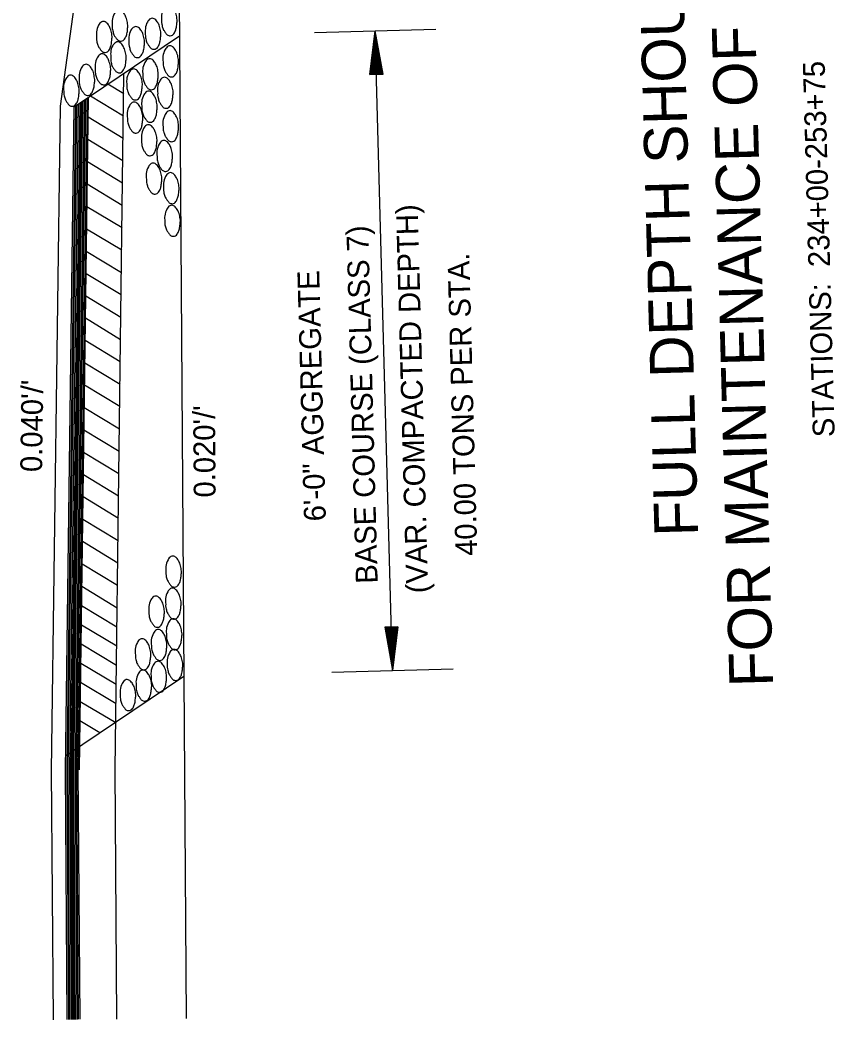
# Model space of a CAD drawing. Extents: x 1926836 to 1933254, y 596317 to 604524.
# Drawn here: x 1932668 to 1932892, y 597228.4 to 597503.4 of the extents above; entities that cross this region are included whole.
import ezdxf

# ---------------------------------------------------------------- set-up
doc = ezdxf.new("R2010")
doc.units = 0
doc.layers.add('Default', color=7, linetype='Continuous')

msp = doc.modelspace()

# ---------------------------------------------------------------- linework, layer by layer
at = {"layer": 'Default'}
for p, q in [((1932679.06, 597479.65), (1932733.75, 597872.49)), ((1932713.69, 597228.79), (1932710.43, 597704.89)), ((1932682.89, 597479.47), (1932711.83, 597498.96)), ((1932748.97, 597499.95), (1932782.32, 597500.85)), ((1932764.17, 597488.36), (1932765.65, 597500.4)), ((1932764.47, 597488.36), (1932765.7, 597498.4)), ((1932770.37, 597324.49), (1932765.65, 597500.4)), ((1932767.77, 597488.45), (1932765.65, 597500.4)), ((1932767.47, 597488.44), (1932765.7, 597498.4)), ((1932764.78, 597488.37), (1932765.75, 597496.33)), ((1932767.16, 597488.44), (1932765.75, 597496.33)), ((1932765.08, 597488.38), (1932765.81, 597494.33)), ((1932766.86, 597488.43), (1932765.81, 597494.33)), ((1932765.39, 597488.39), (1932765.86, 597492.3)), ((1932765.69, 597488.4), (1932765.92, 597490.3)), ((1932766.56, 597488.42), (1932765.86, 597492.3)), ((1932766.25, 597488.41), (1932765.92, 597490.3)), ((1932694.13, 597297.28), (1932696.55, 597488.66)), ((1932764.17, 597488.36), (1932767.77, 597488.45)), ((1932696.48, 597483.08), (1932692.13, 597485.72)), ((1932684.3, 597297.21), (1932686.76, 597482.07)), ((1932696.4, 597476.95), (1932687.31, 597482.44)), ((1932676.65, 597297.01), (1932679.06, 597479.53)), ((1932680.45, 597297.11), (1932682.89, 597479.47)), ((1932680.89, 597297.12), (1932683.33, 597479.76)), ((1932681.22, 597297.13), (1932683.61, 597479.96)), ((1932681.64, 597297.14), (1932684.07, 597480.28)), ((1932682.06, 597297.15), (1932684.46, 597480.51)), ((1932682.42, 597297.16), (1932684.89, 597480.81)), ((1932682.8, 597297.17), (1932685.23, 597481.03)), ((1932683.18, 597297.18), (1932685.66, 597481.37)), ((1932683.6, 597297.19), (1932686.05, 597481.62)), ((1932683.97, 597297.2), (1932686.48, 597481.89)), ((1932696.32, 597470.77), (1932686.66, 597476.64)), ((1932696.24, 597464.61), (1932686.59, 597470.49)), ((1932696.16, 597458.48), (1932686.51, 597464.34)), ((1932696.08, 597452.36), (1932686.43, 597458.21)), ((1932696.01, 597446.18), (1932686.36, 597452.02)), ((1932695.93, 597440.06), (1932686.26, 597445.88)), ((1932695.85, 597433.86), (1932686.17, 597439.74)), ((1932695.78, 597427.77), (1932686.13, 597433.6)), ((1932695.7, 597421.58), (1932686.02, 597427.46)), ((1932695.62, 597415.42), (1932685.96, 597421.34)), ((1932695.54, 597409.33), (1932685.87, 597415.2)), ((1932695.47, 597403.16), (1932685.76, 597409.02)), ((1932695.39, 597397.04), (1932685.67, 597402.93)), ((1932695.32, 597390.82), (1932685.62, 597396.75)), ((1932695.23, 597384.74), (1932685.55, 597390.61)), ((1932695.16, 597378.58), (1932685.45, 597384.47)), ((1932695.08, 597372.42), (1932685.38, 597378.3)), ((1932695.01, 597366.32), (1932685.28, 597372.21)), ((1932694.92, 597360.12), (1932685.19, 597366.03)), ((1932694.84, 597353.98), (1932685.13, 597359.92)), ((1932694.77, 597347.82), (1932685.06, 597353.73)), ((1932694.69, 597341.66), (1932684.98, 597347.59)), ((1932694.62, 597336.44), (1932684.87, 597342.24)), ((1932694.56, 597331.19), (1932684.82, 597336.96)), ((1932771.84, 597336.54), (1932768.25, 597336.44)), ((1932768.25, 597336.44), (1932770.37, 597324.49)), ((1932768.55, 597336.45), (1932770.31, 597326.49)), ((1932768.86, 597336.46), (1932770.26, 597328.56)), ((1932769.16, 597336.46), (1932770.2, 597330.56)), ((1932769.46, 597336.47), (1932770.15, 597332.59)), ((1932769.77, 597336.48), (1932770.1, 597334.59)), ((1932770.33, 597336.5), (1932770.1, 597334.59)), ((1932770.63, 597336.5), (1932770.15, 597332.59)), ((1932770.94, 597336.51), (1932770.2, 597330.56)), ((1932771.23, 597336.52), (1932770.26, 597328.56)), ((1932771.54, 597336.53), (1932770.31, 597326.49)), ((1932771.84, 597336.54), (1932770.37, 597324.49)), ((1932694.49, 597325.89), (1932684.73, 597331.7)), ((1932694.42, 597320.6), (1932684.7, 597326.45)), ((1932680.49, 597301.03), (1932713.03, 597322.95)), ((1932753.69, 597324.05), (1932787.04, 597324.94)), ((1932694.36, 597315.33), (1932684.59, 597321.16)), ((1932694.29, 597310.08), (1932684.53, 597315.9)), ((1932689.94, 597307.39), (1932684.45, 597310.65)), ((1932677.12, 597228.39), (1932676.65, 597297.01)), ((1932680.94, 597228.49), (1932680.45, 597297.11)), ((1932681.36, 597228.5), (1932680.89, 597297.12)), ((1932681.68, 597228.51), (1932681.22, 597297.13)), ((1932682.09, 597228.52), (1932681.64, 597297.14)), ((1932682.49, 597228.53), (1932682.06, 597297.15)), ((1932682.87, 597228.54), (1932682.42, 597297.16)), ((1932683.26, 597228.55), (1932682.8, 597297.17)), ((1932683.65, 597228.56), (1932683.18, 597297.18)), ((1932684.08, 597228.57), (1932683.6, 597297.19)), ((1932684.46, 597228.58), (1932683.97, 597297.2)), ((1932694.62, 597228.66), (1932694.13, 597297.28))]:
    msp.add_line(p, q, dxfattribs=at)
for points in [[(1932706.88, 597503.14), (1932706.88, 597504.68), (1932707.44, 597506.52), (1932708.29, 597507.43), (1932708.78, 597507.56), (1932709.75, 597507.11), (1932710.17, 597506.61), (1932710.67, 597505.65), (1932711.07, 597504.18), (1932711.15, 597503.41), (1932711.09, 597502.31), (1932710.91, 597501.08), (1932710.56, 597500.1), (1932709.89, 597499.2), (1932709.28, 597499.03), (1932708.44, 597499.27), (1932707.9, 597499.94), (1932707.45, 597500.59), (1932707.09, 597501.57), (1932706.95, 597502.21), (1932706.88, 597503.14)], [(1932693.32, 597501.7), (1932693.29, 597503.18), (1932693.88, 597505.04), (1932694.72, 597505.93), (1932695.22, 597506.1), (1932696.16, 597505.66), (1932696.58, 597505.13), (1932697.09, 597504.15), (1932697.51, 597502.7), (1932697.57, 597501.92), (1932697.54, 597500.83), (1932697.37, 597499.58), (1932696.99, 597498.62), (1932696.31, 597497.71), (1932695.73, 597497.55), (1932694.89, 597497.81), (1932694.31, 597498.48), (1932693.86, 597499.08), (1932693.54, 597500.1), (1932693.36, 597500.74), (1932693.32, 597501.7)], [(1932689.01, 597498.56), (1932688.99, 597500.07), (1932689.56, 597501.9), (1932690.41, 597502.84), (1932690.89, 597502.96), (1932691.85, 597502.53), (1932692.27, 597502.01), (1932692.78, 597501.04), (1932693.19, 597499.57), (1932693.27, 597498.82), (1932693.19, 597497.69), (1932693.02, 597496.46), (1932692.68, 597495.48), (1932691.97, 597494.59), (1932691.4, 597494.42), (1932690.58, 597494.66), (1932690, 597495.35), (1932689.57, 597495.98), (1932689.21, 597496.99), (1932689.05, 597497.59), (1932689.01, 597498.56)], [(1932697.91, 597497.13), (1932697.91, 597498.67), (1932698.47, 597500.52), (1932699.31, 597501.43), (1932699.81, 597501.54), (1932700.77, 597501.11), (1932701.2, 597500.6), (1932701.7, 597499.63), (1932702.1, 597498.16), (1932702.18, 597497.41), (1932702.12, 597496.29), (1932701.94, 597495.07), (1932701.59, 597494.1), (1932700.91, 597493.19), (1932700.31, 597493.01), (1932699.47, 597493.26), (1932698.92, 597493.94), (1932698.47, 597494.57), (1932698.12, 597495.57), (1932697.97, 597496.2), (1932697.91, 597497.13)], [(1932702.41, 597499.42), (1932702.42, 597500.96), (1932702.98, 597502.8), (1932703.82, 597503.71), (1932704.32, 597503.84), (1932705.28, 597503.39), (1932705.7, 597502.89), (1932706.21, 597501.93), (1932706.6, 597500.46), (1932706.69, 597499.69), (1932706.62, 597498.59), (1932706.44, 597497.36), (1932706.09, 597496.38), (1932705.42, 597495.48), (1932704.81, 597495.31), (1932703.98, 597495.55), (1932703.44, 597496.22), (1932702.98, 597496.87), (1932702.62, 597497.85), (1932702.48, 597498.48), (1932702.41, 597499.42)], [(1932692.92, 597492.98), (1932692.9, 597494.46), (1932693.44, 597496.31), (1932694.29, 597497.2), (1932694.78, 597497.38), (1932695.74, 597496.93), (1932696.16, 597496.4), (1932696.65, 597495.43), (1932697.07, 597493.98), (1932697.15, 597493.2), (1932697.1, 597492.09), (1932696.94, 597490.85), (1932696.55, 597489.89), (1932695.87, 597488.97), (1932695.3, 597488.83), (1932694.47, 597489.08), (1932693.91, 597489.74), (1932693.46, 597490.36), (1932693.08, 597491.38), (1932692.96, 597492), (1932692.92, 597492.98)], [(1932707.29, 597491.84), (1932707.26, 597493.37), (1932707.85, 597495.21), (1932708.66, 597496.12), (1932709.2, 597496.25), (1932710.13, 597495.82), (1932710.53, 597495.31), (1932711.08, 597494.32), (1932711.46, 597492.87), (1932711.56, 597492.12), (1932711.48, 597491), (1932711.3, 597489.74), (1932710.96, 597488.78), (1932710.25, 597487.88), (1932709.68, 597487.71), (1932708.85, 597487.95), (1932708.3, 597488.64), (1932707.86, 597489.27), (1932707.49, 597490.28), (1932707.33, 597490.9), (1932707.29, 597491.84)], [(1932688.63, 597489.65), (1932688.61, 597491.16), (1932689.18, 597492.99), (1932690.02, 597493.91), (1932690.52, 597494.08), (1932691.47, 597493.63), (1932691.9, 597493.11), (1932692.38, 597492.13), (1932692.81, 597490.66), (1932692.89, 597489.9), (1932692.84, 597488.78), (1932692.65, 597487.55), (1932692.3, 597486.59), (1932691.61, 597485.69), (1932691.02, 597485.52), (1932690.21, 597485.76), (1932689.61, 597486.43), (1932689.17, 597487.06), (1932688.83, 597488.08), (1932688.67, 597488.7), (1932688.63, 597489.65)], [(1932684.23, 597486.77), (1932684.2, 597488.27), (1932684.79, 597490.11), (1932685.61, 597491.05), (1932686.13, 597491.19), (1932687.07, 597490.73), (1932687.5, 597490.2), (1932688.03, 597489.26), (1932688.38, 597487.75), (1932688.51, 597487.02), (1932688.42, 597485.88), (1932688.25, 597484.67), (1932687.89, 597483.72), (1932687.22, 597482.8), (1932686.61, 597482.62), (1932685.8, 597482.89), (1932685.22, 597483.56), (1932684.78, 597484.2), (1932684.44, 597485.18), (1932684.27, 597485.79), (1932684.23, 597486.77)], [(1932701.72, 597488.3), (1932701.69, 597489.83), (1932702.28, 597491.67), (1932703.09, 597492.58), (1932703.62, 597492.72), (1932704.55, 597492.28), (1932704.96, 597491.77), (1932705.5, 597490.79), (1932705.88, 597489.34), (1932705.98, 597488.58), (1932705.9, 597487.47), (1932705.73, 597486.2), (1932705.38, 597485.24), (1932704.68, 597484.34), (1932704.1, 597484.18), (1932703.27, 597484.41), (1932702.73, 597485.1), (1932702.29, 597485.73), (1932701.91, 597486.74), (1932701.76, 597487.37), (1932701.72, 597488.3)], [(1932679.98, 597483.78), (1932679.95, 597485.3), (1932680.54, 597487.14), (1932681.35, 597488.05), (1932681.88, 597488.19), (1932682.81, 597487.75), (1932683.22, 597487.24), (1932683.77, 597486.26), (1932684.14, 597484.81), (1932684.24, 597484.05), (1932684.16, 597482.94), (1932683.99, 597481.67), (1932683.64, 597480.71), (1932682.94, 597479.81), (1932682.36, 597479.65), (1932681.54, 597479.89), (1932680.99, 597480.57), (1932680.55, 597481.2), (1932680.17, 597482.21), (1932680.02, 597482.84), (1932679.98, 597483.78)], [(1932697.33, 597485.49), (1932697.3, 597487.02), (1932697.89, 597488.86), (1932698.7, 597489.77), (1932699.24, 597489.9), (1932700.17, 597489.47), (1932700.57, 597488.96), (1932701.12, 597487.97), (1932701.5, 597486.52), (1932701.6, 597485.76), (1932701.52, 597484.65), (1932701.34, 597483.39), (1932701, 597482.43), (1932700.29, 597481.53), (1932699.72, 597481.36), (1932698.89, 597481.6), (1932698.34, 597482.29), (1932697.9, 597482.91), (1932697.53, 597483.92), (1932697.37, 597484.55), (1932697.33, 597485.49)], [(1932705.81, 597483.21), (1932705.77, 597484.74), (1932706.36, 597486.57), (1932707.17, 597487.49), (1932707.71, 597487.62), (1932708.64, 597487.19), (1932709.04, 597486.68), (1932709.59, 597485.69), (1932709.97, 597484.24), (1932710.07, 597483.48), (1932709.99, 597482.37), (1932709.81, 597481.1), (1932709.47, 597480.15), (1932708.76, 597479.25), (1932708.19, 597479.08), (1932707.36, 597479.32), (1932706.81, 597480), (1932706.37, 597480.63), (1932706, 597481.64), (1932705.84, 597482.27), (1932705.81, 597483.21)], [(1932701.44, 597479.38), (1932701.41, 597480.91), (1932702, 597482.74), (1932702.81, 597483.65), (1932703.34, 597483.79), (1932704.28, 597483.35), (1932704.68, 597482.84), (1932705.23, 597481.86), (1932705.6, 597480.41), (1932705.71, 597479.65), (1932705.62, 597478.54), (1932705.45, 597477.27), (1932705.1, 597476.31), (1932704.4, 597475.41), (1932703.82, 597475.25), (1932703, 597475.49), (1932702.45, 597476.17), (1932702.01, 597476.8), (1932701.63, 597477.81), (1932701.48, 597478.44), (1932701.44, 597479.38)], [(1932697.48, 597476.36), (1932697.44, 597477.89), (1932698.04, 597479.73), (1932698.84, 597480.64), (1932699.38, 597480.78), (1932700.31, 597480.34), (1932700.71, 597479.83), (1932701.26, 597478.85), (1932701.64, 597477.4), (1932701.74, 597476.64), (1932701.66, 597475.53), (1932701.48, 597474.26), (1932701.14, 597473.3), (1932700.43, 597472.4), (1932699.86, 597472.24), (1932699.03, 597472.47), (1932698.48, 597473.16), (1932698.05, 597473.79), (1932697.67, 597474.8), (1932697.51, 597475.42), (1932697.48, 597476.36)], [(1932707.3, 597474.02), (1932707.27, 597475.55), (1932707.86, 597477.39), (1932708.67, 597478.3), (1932709.2, 597478.44), (1932710.14, 597478), (1932710.54, 597477.49), (1932711.09, 597476.51), (1932711.47, 597475.06), (1932711.57, 597474.3), (1932711.49, 597473.19), (1932711.31, 597471.92), (1932710.97, 597470.96), (1932710.26, 597470.06), (1932709.68, 597469.9), (1932708.86, 597470.13), (1932708.31, 597470.82), (1932707.87, 597471.45), (1932707.49, 597472.46), (1932707.34, 597473.09), (1932707.3, 597474.02)], [(1932701.38, 597470.14), (1932701.35, 597471.67), (1932701.94, 597473.51), (1932702.74, 597474.42), (1932703.28, 597474.55), (1932704.21, 597474.12), (1932704.62, 597473.61), (1932705.16, 597472.62), (1932705.54, 597471.17), (1932705.64, 597470.42), (1932705.56, 597469.3), (1932705.39, 597468.04), (1932705.04, 597467.08), (1932704.33, 597466.18), (1932703.76, 597466.01), (1932702.93, 597466.25), (1932702.38, 597466.94), (1932701.95, 597467.57), (1932701.57, 597468.58), (1932701.41, 597469.2), (1932701.38, 597470.14)], [(1932705.64, 597465.85), (1932705.61, 597467.38), (1932706.2, 597469.21), (1932707.01, 597470.13), (1932707.54, 597470.26), (1932708.48, 597469.82), (1932708.88, 597469.32), (1932709.43, 597468.33), (1932709.8, 597466.88), (1932709.91, 597466.12), (1932709.82, 597465.01), (1932709.65, 597463.74), (1932709.3, 597462.78), (1932708.6, 597461.89), (1932708.02, 597461.72), (1932707.2, 597461.96), (1932706.65, 597462.64), (1932706.21, 597463.27), (1932705.83, 597464.28), (1932705.68, 597464.91), (1932705.64, 597465.85)], [(1932702.7, 597459.59), (1932702.67, 597461.12), (1932703.26, 597462.96), (1932704.06, 597463.87), (1932704.6, 597464.01), (1932705.53, 597463.57), (1932705.94, 597463.06), (1932706.48, 597462.08), (1932706.86, 597460.63), (1932706.96, 597459.87), (1932706.88, 597458.76), (1932706.71, 597457.49), (1932706.36, 597456.53), (1932705.66, 597455.63), (1932705.08, 597455.47), (1932704.25, 597455.7), (1932703.7, 597456.39), (1932703.27, 597457.02), (1932702.89, 597458.03), (1932702.73, 597458.66), (1932702.7, 597459.59)], [(1932707.44, 597456.98), (1932707.41, 597458.51), (1932708, 597460.35), (1932708.81, 597461.26), (1932709.34, 597461.39), (1932710.27, 597460.96), (1932710.68, 597460.45), (1932711.22, 597459.46), (1932711.6, 597458.01), (1932711.7, 597457.26), (1932711.62, 597456.14), (1932711.45, 597454.88), (1932711.1, 597453.92), (1932710.4, 597453.02), (1932709.82, 597452.85), (1932708.99, 597453.09), (1932708.45, 597453.78), (1932708.01, 597454.41), (1932707.63, 597455.42), (1932707.47, 597456.04), (1932707.44, 597456.98)], [(1932707.78, 597448.01), (1932707.75, 597449.54), (1932708.34, 597451.37), (1932709.15, 597452.29), (1932709.68, 597452.42), (1932710.62, 597451.99), (1932711.02, 597451.48), (1932711.57, 597450.49), (1932711.94, 597449.04), (1932712.05, 597448.28), (1932711.97, 597447.17), (1932711.79, 597445.91), (1932711.44, 597444.95), (1932710.74, 597444.05), (1932710.16, 597443.88), (1932709.34, 597444.12), (1932708.79, 597444.8), (1932708.35, 597445.43), (1932707.97, 597446.44), (1932707.82, 597447.07), (1932707.78, 597448.01)], [(1932708.09, 597351.54), (1932708.06, 597353.07), (1932708.65, 597354.9), (1932709.45, 597355.82), (1932709.99, 597355.95), (1932710.92, 597355.52), (1932711.33, 597355.01), (1932711.87, 597354.02), (1932712.25, 597352.57), (1932712.35, 597351.81), (1932712.27, 597350.7), (1932712.1, 597349.43), (1932711.75, 597348.48), (1932711.05, 597347.58), (1932710.47, 597347.41), (1932709.64, 597347.65), (1932709.09, 597348.33), (1932708.66, 597348.96), (1932708.28, 597349.97), (1932708.12, 597350.6), (1932708.09, 597351.54)], [(1932703.4, 597340.52), (1932703.37, 597342.05), (1932703.96, 597343.89), (1932704.77, 597344.8), (1932705.31, 597344.93), (1932706.24, 597344.5), (1932706.64, 597343.99), (1932707.19, 597343), (1932707.57, 597341.55), (1932707.67, 597340.79), (1932707.59, 597339.68), (1932707.41, 597338.42), (1932707.07, 597337.46), (1932706.36, 597336.56), (1932705.79, 597336.39), (1932704.96, 597336.63), (1932704.41, 597337.32), (1932703.97, 597337.94), (1932703.6, 597338.95), (1932703.44, 597339.58), (1932703.4, 597340.52)], [(1932708.01, 597342.74), (1932707.97, 597344.27), (1932708.57, 597346.1), (1932709.37, 597347.01), (1932709.91, 597347.15), (1932710.84, 597346.71), (1932711.24, 597346.2), (1932711.79, 597345.22), (1932712.17, 597343.77), (1932712.27, 597343.01), (1932712.19, 597341.9), (1932712.01, 597340.63), (1932711.67, 597339.67), (1932710.96, 597338.77), (1932710.39, 597338.61), (1932709.56, 597338.85), (1932709.01, 597339.53), (1932708.57, 597340.16), (1932708.2, 597341.17), (1932708.04, 597341.8), (1932708.01, 597342.74)], [(1932708.23, 597334.3), (1932708.2, 597335.83), (1932708.79, 597337.67), (1932709.6, 597338.58), (1932710.13, 597338.71), (1932711.07, 597338.28), (1932711.47, 597337.77), (1932712.02, 597336.78), (1932712.4, 597335.33), (1932712.5, 597334.57), (1932712.42, 597333.46), (1932712.24, 597332.2), (1932711.9, 597331.24), (1932711.19, 597330.34), (1932710.61, 597330.17), (1932709.79, 597330.41), (1932709.24, 597331.1), (1932708.8, 597331.72), (1932708.42, 597332.73), (1932708.27, 597333.36), (1932708.23, 597334.3)], [(1932704.09, 597331.38), (1932704.06, 597332.91), (1932704.65, 597334.74), (1932705.45, 597335.66), (1932705.99, 597335.79), (1932706.92, 597335.35), (1932707.33, 597334.85), (1932707.87, 597333.86), (1932708.25, 597332.41), (1932708.35, 597331.65), (1932708.27, 597330.54), (1932708.1, 597329.27), (1932707.75, 597328.31), (1932707.05, 597327.42), (1932706.47, 597327.25), (1932705.64, 597327.49), (1932705.1, 597328.17), (1932704.66, 597328.8), (1932704.28, 597329.81), (1932704.12, 597330.44), (1932704.09, 597331.38)], [(1932699.67, 597328.8), (1932699.64, 597330.33), (1932700.23, 597332.17), (1932701.04, 597333.08), (1932701.58, 597333.21), (1932702.51, 597332.78), (1932702.91, 597332.27), (1932703.46, 597331.28), (1932703.84, 597329.83), (1932703.94, 597329.07), (1932703.86, 597327.96), (1932703.68, 597326.7), (1932703.34, 597325.74), (1932702.63, 597324.84), (1932702.06, 597324.67), (1932701.23, 597324.91), (1932700.68, 597325.6), (1932700.24, 597326.22), (1932699.87, 597327.24), (1932699.71, 597327.86), (1932699.67, 597328.8)], [(1932708.46, 597325.87), (1932708.43, 597327.4), (1932709.02, 597329.24), (1932709.82, 597330.15), (1932710.36, 597330.28), (1932711.29, 597329.85), (1932711.7, 597329.34), (1932712.24, 597328.35), (1932712.62, 597326.9), (1932712.72, 597326.15), (1932712.64, 597325.03), (1932712.47, 597323.77), (1932712.12, 597322.81), (1932711.42, 597321.91), (1932710.84, 597321.74), (1932710.01, 597321.98), (1932709.46, 597322.67), (1932709.03, 597323.3), (1932708.65, 597324.31), (1932708.49, 597324.93), (1932708.46, 597325.87)], [(1932704.01, 597322.62), (1932703.98, 597324.15), (1932704.57, 597325.99), (1932705.38, 597326.9), (1932705.92, 597327.03), (1932706.85, 597326.6), (1932707.25, 597326.09), (1932707.8, 597325.1), (1932708.18, 597323.65), (1932708.28, 597322.9), (1932708.2, 597321.78), (1932708.02, 597320.52), (1932707.68, 597319.56), (1932706.97, 597318.66), (1932706.4, 597318.49), (1932705.57, 597318.73), (1932705.02, 597319.42), (1932704.58, 597320.05), (1932704.21, 597321.06), (1932704.05, 597321.68), (1932704.01, 597322.62)], [(1932699.9, 597320.2), (1932699.87, 597321.73), (1932700.46, 597323.56), (1932701.27, 597324.47), (1932701.81, 597324.61), (1932702.74, 597324.17), (1932703.14, 597323.66), (1932703.69, 597322.68), (1932704.07, 597321.23), (1932704.17, 597320.47), (1932704.09, 597319.36), (1932703.91, 597318.09), (1932703.57, 597317.13), (1932702.86, 597316.23), (1932702.29, 597316.07), (1932701.46, 597316.31), (1932700.91, 597316.99), (1932700.47, 597317.62), (1932700.1, 597318.63), (1932699.94, 597319.26), (1932699.9, 597320.2)], [(1932695.51, 597317.59), (1932695.48, 597319.12), (1932696.07, 597320.95), (1932696.88, 597321.87), (1932697.42, 597322), (1932698.35, 597321.57), (1932698.75, 597321.06), (1932699.3, 597320.07), (1932699.68, 597318.62), (1932699.78, 597317.86), (1932699.7, 597316.75), (1932699.52, 597315.49), (1932699.18, 597314.53), (1932698.47, 597313.63), (1932697.9, 597313.46), (1932697.07, 597313.7), (1932696.52, 597314.38), (1932696.08, 597315.01), (1932695.71, 597316.02), (1932695.55, 597316.65), (1932695.51, 597317.59)]]:
    msp.add_spline(points, degree=3, dxfattribs=at)

# ---------------------------------------------------------------- texts
for s, height, rotation, p in [('FOR MAINTENANCE OF TRAFFIC', 12, 91.5377, (1932875.04, 597320.1)), ('FULL DEPTH SHOULDER', 12, 91.5377, (1932854.42, 597361.51)), ('STATIONS:  234+00-253+75', 6, 91.5377, (1932891.98, 597388.72)), ('(VAR. COMPACTED DEPTH)', 6, 91.5377, (1932780.18, 597345.8)), ('BASE COURSE (CLASS 7)', 6, 91.5377, (1932766.32, 597348.43)), ('40.00 TONS PER STA.', 6, 91.5377, (1932793.7, 597356.07)), ('6\'-0" AGGREGATE', 6, 91.5377, (1932752.06, 597365.58)), ("0.040'/'", 6, 89.2454, (1932674.03, 597379.03)), ("0.020'/'", 6, 90.392, (1932721.74, 597372.07))]:
    msp.add_text(s, height=height, rotation=rotation, dxfattribs=at).set_placement(p)

doc.saveas('drawing.dxf')
